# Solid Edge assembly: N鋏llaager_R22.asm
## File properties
Author: Türk
Template: Iso Assembly.asm
Last saved by: Türk
Revision: 12
Application: Solid Edge
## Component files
lss.par
el.par
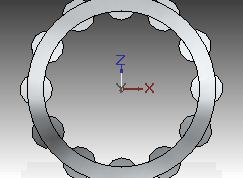
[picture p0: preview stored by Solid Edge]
